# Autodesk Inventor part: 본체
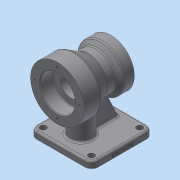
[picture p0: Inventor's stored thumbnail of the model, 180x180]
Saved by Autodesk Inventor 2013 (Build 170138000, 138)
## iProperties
Created: 2019-01
Part Number: 본체
Material: 일반
Document SubType Name: Modeling
Designer: dgall
Density: 1 g/cm^3
Author: dgall
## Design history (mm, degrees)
sketch "스케치1"
  geometry: L1 (0, 0)-(80, 0); L2 (0, 0)-(0, 40); L3 (0, 40)-(25, 40); L4 (25, 40)-(45.785, 28); L5 (45.785, 28)-(59.126, 28); L6 (59.126, 28)-(65, 35); L7 (65, 35)-(80, 35); L8 (80, 35)-(80, 0); L9 (0, 26)-(20, 26); L10 (20, 26)-(20, 16); L11 (20, 16)-(63, 16); L12 (63, 16)-(63, 20); L13 (63, 20)-(80, 20)
  constraints: 26 end point, 6 perpendicular, 4 parallel, 2 point on line, 1 horizontal
  dimensions: "d0" = 80 distance of L1.start L1.end; "d1" = 80 diameter of L3 L1; "d2" = 56 diameter of L5 L1; "d3" = 70 diameter of L7 L1; "d4" = 25 distance of L2.end L3.end; "d5" = 15 distance of L6.end L7.end; "d7" = 30 deg angle of L5 L4; "d8" = 50 deg angle of L5 L6; "d9" = 20 distance of L9.start L9.end; "d10" = 17 distance of L12.end L13.end; "d11" = 52 diameter of L9 L1; "d12" = 40 diameter of L13 L1; "d13" = 32 diameter of L11 L1
revolve "회전1" sketch "스케치1" stored, may be unused: angle "d14" = 90 deg
node "작업 평면1"
sketch "스케치2"
  geometry: L1 (-5, -46)-(-97, -46); L2 (-97, -46)-(-97, 46); L3 (-97, 46)-(-5, 46); L4 (-5, 46)-(-5, -46); L5 (0, 40)-(0, -40) reference; 2 further points
  constraints: 8 end point, 2 parallel, 1 horizontal, 1 horizontal alignment, 1 midpoint, 1 perpendicular
  dimensions: "d16" = 92 distance of L2.end L3.end; "d17" = 92 distance of L1.end L2.end; "d18" = 5 distance between parallel lines of L4 L5
extrude "돌출1" join sketch "스케치2" distance "d19" = 10; taper "d20" = 0 deg
sketch "스케치3"
  geometry: L1 (5, 46)-(5, -46) reference; C1 r 16 at (35, 0); 1 further point
  constraints: 1 centre point, 1 horizontal alignment
  dimensions: "d21" = 32 diameter of C1; "d22" = 30 distance from line of L1 C1.centre
extrude "돌출2" join sketch "스케치3" stored distance "d23" = 10; taper "d24" = 0 deg
sketch "스케치4"
  geometry: L1 (51, -70)-(51, -28) reference; L2 (51, -28)-(59.126, -28) reference; L3 (97, -70)-(5, -70) reference; L4 (59.126, -28)-(65, -35) reference; L5 (65, -35)-(80, -35) reference; L6 (70.679, -35)-(87, -70); L7 (97, -80)-(97, -70) reference; 1 further point
  constraints: 2 end point, 2 point on line
  dimensions: "d25" = 10 distance of L3.start L6.end; "d26" = 25 deg angle of L7 L6
feature "리브1" sketch "스케치4" dims "d27" = 1, "d28" = 10, "d29" = 0, "d30" = 0, "d31" = 1, "d32" = 1
fillet "모깎기1" dims "d33" = 10
sketch "스케치5"
  geometry: C1 r 4.5 at (15, 36); C2 r 4.5 at (87, 36); C3 r 4.5 at (87, -36); C4 r 4.5 at (15, -36); A1 r 10 centre (87, 36) between (97, 36) and (87, 46) reference; A2 r 10 centre (15, 36) between (15, 46) and (5, 36) reference; A3 r 10 centre (15, -36) between (5, -36) and (15, -46) reference; A4 r 10 centre (87, -36) between (87, -46) and (97, -36) reference; 1 further point
  constraints: 4 centre point, 4 coincident
  dimensions: "d34" = 9 diameter of C1; "d35" = 9 diameter of C2; "d36" = 9 diameter of C3; "d37" = 9 diameter of C4
extrude "돌출3" cut sketch "스케치5" stored distance "d38" = 10; taper "d39" = 0 deg
fillet "모깎기2" dims "d40" = 3
fillet "모깎기3" dims "d41" = 3
fillet "모깎기4" dims "d42" = 3
sketch "스케치6"
  geometry: C1 r 26 at (0, 0) reference; 4 further points
  constraints: 5 other
  dimensions: "d43" = 33 distance of C1.centre point (0, 33); "d46" = 360 deg dimension on C1.centre point (0, 33) (derived)
hole "구멍1" sketch "스케치6" at (0, 33), (-33, 0), (0, -33), (33, 0) diameter "d48" = 3.242; stored, may be unused: countersink angle "d52" = 90 deg, drill point angle "d54" = 118 deg; dims "d49" = 9, "d50" = 4, "d51" = 2, "d53" = 11
sketch "스케치7"
  geometry: C1 r 20 at (0, 0) reference; 4 further points
  constraints: 1 vertical alignment, 5 other
  dimensions: "d55" = 27.5 distance of C1.centre point (0, 27.5); "d58" = 360 deg dimension on C1.centre point (0, 27.5) (derived)
hole "구멍2" sketch "스케치7" at (0, 27.5), (-27.5, 0), (0, -27.5), (27.5, 0) diameter "d60" = 3.242; stored, may be unused: countersink angle "d64" = 90 deg, drill point angle "d66" = 118 deg; dims "d61" = 9, "d62" = 4, "d63" = 2, "d65" = 11
chamfer "모따기1" distance "d67" = 1; stored, may be unused: second distance "d68" = 2, angle "d69" = 45 deg
fillet "모깎기5" dims "d70" = 0.6
fillet "모깎기6" dims "d71" = 1
node "작업 평면2"
sketch "스케치8"
  geometry: L1 (-10, 7)-(-10, 0) reference; L2 (82, 0)-(72, 0) reference; 2 further points
  constraints: 1 other
  dimensions: "d73" = 46 distance from line of L1 point (36, 4); "d74" = 4 distance from line of L2 point (36, 4)
feature "엠보싱1" sketch "스케치8" dims "d0" = 80, "d1" = 80, "d2" = 56, "d3" = 70, "d4" = 25, "d5" = 15, "d7" = 30 deg, "d8" = 50 deg, "d9" = 20, "d10" = 17, "d11" = 52, "d12" = 40, "d13" = 32, "d75" = 0.5, "d76" = 0
node "솔리드1"
other parameters: "d72" = 31.25
